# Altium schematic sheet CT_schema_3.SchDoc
size 276 x 169 mm
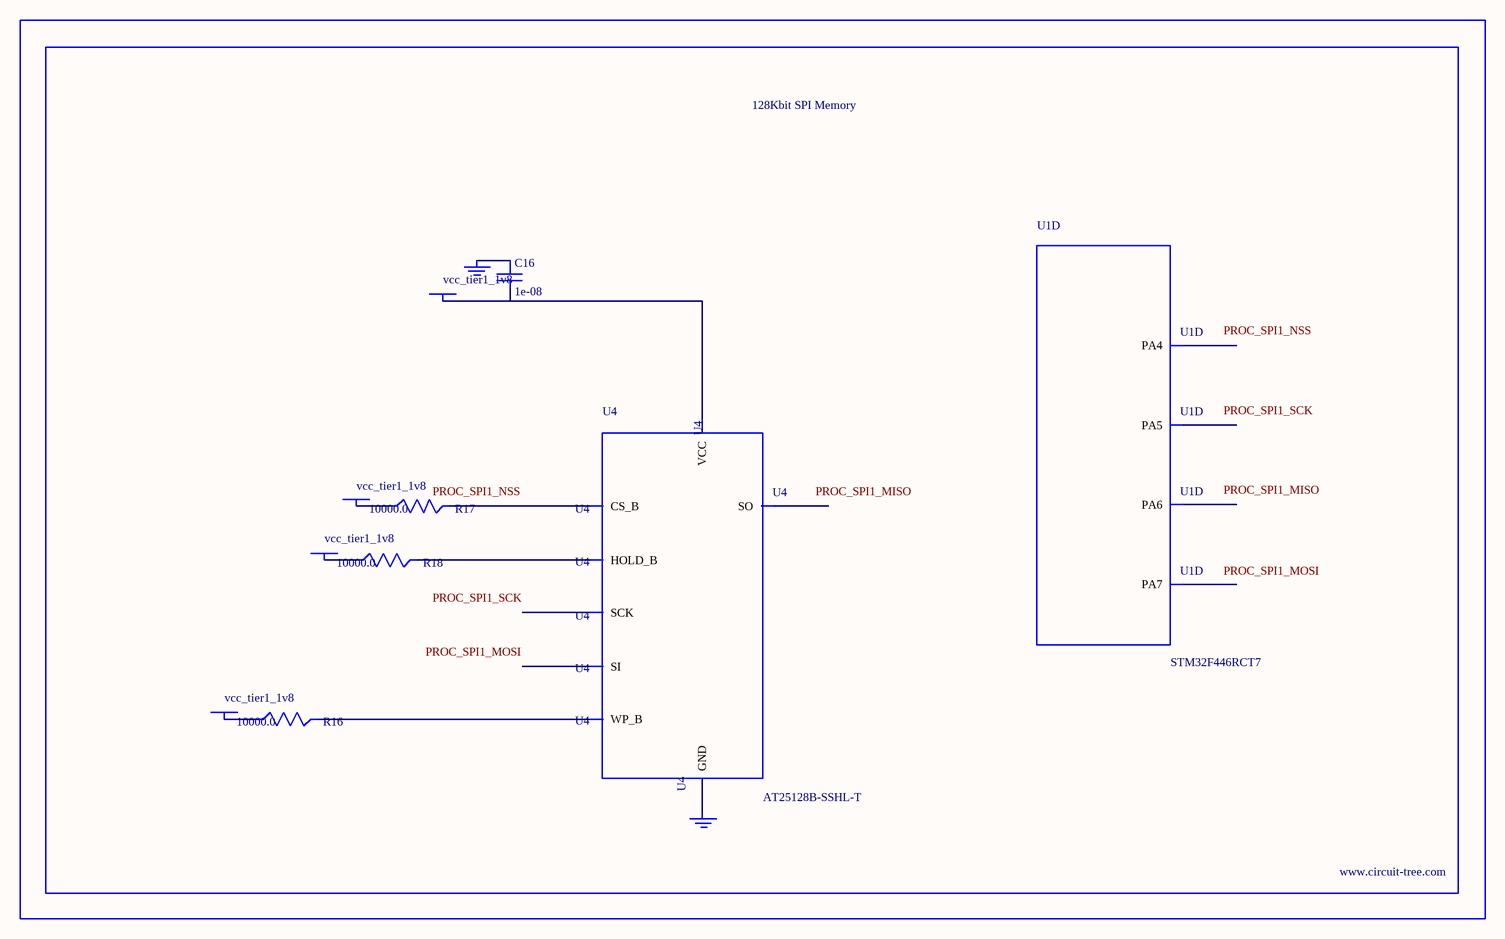
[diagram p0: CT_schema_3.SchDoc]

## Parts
BORDER2  (no value)
C16  1e-08  [C0402]
GND_INSTANCE_2_0  (no value)
GND_INSTANCE_2_1  (no value)
POWER_INSTANCE_2_0  vcc_tier1_1v8
POWER_INSTANCE_2_1  vcc_tier1_1v8
POWER_INSTANCE_2_2  vcc_tier1_1v8
POWER_INSTANCE_2_3  vcc_tier1_1v8
R16  10000.0  [R0603]
R17  10000.0  [R0603]
R18  10000.0  [R0603]
U1  STM32F446RCT7  [LQFP64]  (part D of 7)
U4  AT25128B-SSHL-T  [SOIC-8]

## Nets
NetC16_1: C16.1 GND_INSTANCE_2_0.0(GND)
NetC16_2: C16.2 POWER_INSTANCE_2_3.0(PWR) U4.8(VCC)
NetGND_INSTANCE_2_1_0: GND_INSTANCE_2_1.0(GND) U4.4(GND)
NetPOWER_INSTANCE_2_0_0: POWER_INSTANCE_2_0.0(PWR) R17.1
NetPOWER_INSTANCE_2_1_0: POWER_INSTANCE_2_1.0(PWR) R16.1
NetPOWER_INSTANCE_2_2_0: POWER_INSTANCE_2_2.0(PWR) R18.1
NetR16_2: R16.2 U4.3(WP_B)
NetR17_2: R17.2 U4.1(CS_B)
NetR18_2: R18.2 U4.7(HOLD_B)

Not connected (* = marked no-connect by the designer): U1 20(PA4) 21(PA5) 22(PA6) 23(PA7); U4 2(SO) 5(SI) 6(SCK)

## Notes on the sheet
- Labels drawn without touching a wire or pin: PROC_SPI1_MISO, PROC_SPI1_MOSI, PROC_SPI1_NSS, PROC_SPI1_SCK

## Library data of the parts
BORDER2 = BORDER_PAGE2
C16 = C0402C103K3RAC
GND_INSTANCE_2_0 GND_INSTANCE_2_1 = GND
POWER_INSTANCE_2_0-POWER_INSTANCE_2_3 = PWR
R16-R18 = RC0603JR-0710KL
